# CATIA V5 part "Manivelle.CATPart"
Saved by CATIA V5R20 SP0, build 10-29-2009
Part number: Manivelle
Bounding box of the stored display mesh (mm): x -1 to 0, y 8 to 12, z 13 to 22
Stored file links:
  C:\Users\J\IAO_2012_jgossard\Manivelle.CATPart
  C:\Users\J\IAO_2012_jgossard\jgossard.CATProduct
  C:\Users\J\IAO_2012_jgossard\Bati.CATPart
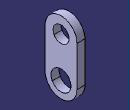
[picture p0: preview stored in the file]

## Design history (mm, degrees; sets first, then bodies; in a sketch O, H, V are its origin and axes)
Set1
  Plane1 "Plan_ref": linked copy from another document
  Point1 "Point_A": linked copy from another document
  Point2 "Point_B": linked copy from another document
  Point3 "Point_A": linked copy from another document
Body1 (main body)
  Sketch1 on Plane1, origin (0, 0, 0), H (0, 1, 0), V (0, 0, 1)
    construction line L1 (10, 15) -> (10, 20)
    point P1 (10, 15)
    point P2 (10, 20)
    line L2 (8, 15) -> (8, 20)
    line L3 (12, 20) -> (12, 15)
    arc A1 centre (10, 20) radius 2 from (8, 20) to (12, 20) cw
    arc A2 centre (10, 15) radius 2 from (12, 15) to (8, 15) cw
    reference projected point E1 (10, 15) from Point1
    reference projected point E2 (10, 20) from Point2
    distance L1 L2 = 2
    vertical: L1 V
    tangency: A1 L2, A2 L2, A1 L3, A2 L3
    coincidence: P1 E1, P2 E2
  Pad1: profile Sketch1, direction (-1, 0, 0), length 1
  Sketch2 on end face of Pad1, origin (-1, 11.0301, 7.4247), H (0, -1, 0), V (0, 0, 1)
    point P1 (1.0301, 7.5753)
    reference projected point E1 (1.0301, 7.5753) from Point3
    coincidence: P1 E1
  Hole1: placed by Sketch2, at (-1, 10, 15) direction (1, 0, 0), diameter 2.5, through (limit type 6)
  Sketch3 on end face of Pad1, origin (-1, 11.2684, 14.0715), H (0, -1, 0), V (0, 0, 1)
    point P1 (1.2684, 5.9285)
    reference projected point E1 (1.2684, 5.9285) from Point2
    coincidence: P1 E1
  Hole2: placed by Sketch3, at (-1, 10, 20) direction (1, 0, 0), diameter 2, through (limit type 6)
